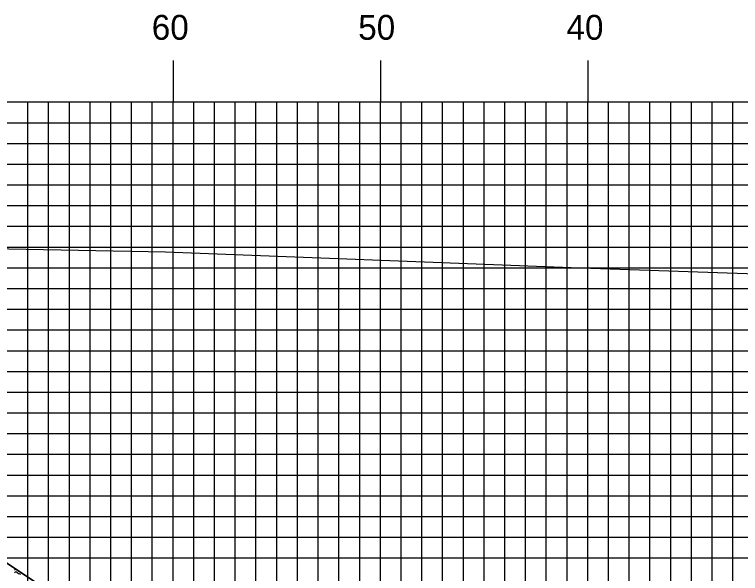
# Model space of a CAD drawing. Extents: x 1770055 to 1770398, y 442591 to 442811.
# Drawn here: x 1770152.88 to 1770187.89, y 442710.92 to 442737.88 of the extents above; entities that cross this region are included whole.
import ezdxf

# ---------------------------------------------------------------- set-up
doc = ezdxf.new("R2010")
doc.units = 0
for name, color, linetype in [('D_Roadway_Centerline', 7, 'Continuous'), ('D_Roadway_SlopeLines', 7, 'Continuous'), ('GRUBBING IN FILL', 7, 'Continuous'), ('H_V ANNOTATION', 7, 'Continuous'), ('MAJOR', 7, 'Continuous'), ('MINOR', 7, 'Continuous'), ('S_Roadway_Centerline', 7, 'Continuous')]:
    doc.layers.add(name, color=color, linetype=linetype)

msp = doc.modelspace()

# ---------------------------------------------------------------- linework, layer by layer
at = {"layer": 'D_Roadway_Centerline'}
msp.add_lwpolyline([(1770126.762, 442726.961), (1770128.012, 442726.836), (1770129.262, 442726.509), (1770130.512, 442725.979), (1770131.761, 442725.247), (1770143.721, 442717.274), (1770186.354, 442688.852), (1770190.354, 442689.852), (1770200.525, 442692.396), (1770200.528, 442692.396), (1770208.529, 442692.716), (1770210.349, 442692.753), (1770220.528, 442692.956), (1770232.528, 442692.716), (1770240.528, 442692.396), (1770250.702, 442689.852), (1770254.136, 442688.994)], dxfattribs=at)
at = {"layer": 'D_Roadway_SlopeLines'}
msp.add_lwpolyline([(1770186.354, 442688.852), (1770131.761, 442725.247), (1770130.512, 442725.979), (1770129.262, 442726.509), (1770128.012, 442726.836), (1770126.762, 442726.961)], dxfattribs=at)
at = {"layer": 'GRUBBING IN FILL'}
for p, q in [((1770152.947, 442711.123), (1770152.882, 442711.084)), ((1770152.882, 442710.95), (1770152.91, 442710.975)), ((1770152.995, 442710.979), (1770153.073, 442710.923)), ((1770153.085, 442710.917), (1770153.174, 442710.878))]:
    msp.add_line(p, q, dxfattribs=at)
for centre, major_axis, end_param in [((1770152.955, 442710.923), (0, 0.0683), 7.003256), ((1770153.113, 442710.979), (0, -0.0683), 5.870775)]:
    msp.add_ellipse(centre, major_axis=major_axis, ratio=0.99895, start_param=5.668522, end_param=end_param, dxfattribs=at)
at = {"layer": 'MAJOR'}
for p, q in [((1770160.528, 442735.669), (1770160.528, 442733.665)), ((1770170.528, 442735.669), (1770170.528, 442733.665)), ((1770180.528, 442735.669), (1770180.528, 442733.665)), ((1770080.528, 442733.665), (1770360.528, 442733.665)), ((1770080.528, 442733.665), (1770360.528, 442733.665)), ((1770160.528, 442683.665), (1770160.528, 442733.665)), ((1770170.528, 442683.665), (1770170.528, 442733.665)), ((1770180.528, 442683.665), (1770180.528, 442733.665)), ((1770080.528, 442728.665), (1770360.528, 442728.665)), ((1770080.528, 442723.665), (1770360.528, 442723.665)), ((1770080.528, 442718.665), (1770360.528, 442718.665)), ((1770080.528, 442713.665), (1770360.528, 442713.665))]:
    msp.add_line(p, q, dxfattribs=at)
at = {"layer": 'MINOR'}
for p, q in [((1770153.528, 442683.665), (1770153.528, 442733.665)), ((1770154.528, 442683.665), (1770154.528, 442733.665)), ((1770155.528, 442683.665), (1770155.528, 442733.665)), ((1770156.528, 442683.665), (1770156.528, 442733.665)), ((1770157.528, 442683.665), (1770157.528, 442733.665)), ((1770158.528, 442683.665), (1770158.528, 442733.665)), ((1770159.528, 442683.665), (1770159.528, 442733.665)), ((1770161.528, 442683.665), (1770161.528, 442733.665)), ((1770162.528, 442683.665), (1770162.528, 442733.665)), ((1770163.528, 442683.665), (1770163.528, 442733.665)), ((1770164.528, 442683.665), (1770164.528, 442733.665)), ((1770165.528, 442683.665), (1770165.528, 442733.665)), ((1770166.528, 442683.665), (1770166.528, 442733.665)), ((1770167.528, 442683.665), (1770167.528, 442733.665)), ((1770168.528, 442683.665), (1770168.528, 442733.665)), ((1770169.528, 442683.665), (1770169.528, 442733.665)), ((1770171.528, 442683.665), (1770171.528, 442733.665)), ((1770172.528, 442683.665), (1770172.528, 442733.665)), ((1770173.528, 442683.665), (1770173.528, 442733.665)), ((1770174.528, 442683.665), (1770174.528, 442733.665)), ((1770175.528, 442683.665), (1770175.528, 442733.665)), ((1770176.528, 442683.665), (1770176.528, 442733.665)), ((1770177.528, 442683.665), (1770177.528, 442733.665)), ((1770178.528, 442683.665), (1770178.528, 442733.665)), ((1770179.528, 442683.665), (1770179.528, 442733.665)), ((1770181.528, 442683.665), (1770181.528, 442733.665)), ((1770182.528, 442683.665), (1770182.528, 442733.665)), ((1770183.528, 442683.665), (1770183.528, 442733.665)), ((1770184.528, 442683.665), (1770184.528, 442733.665)), ((1770185.528, 442683.665), (1770185.528, 442733.665)), ((1770186.528, 442683.665), (1770186.528, 442733.665)), ((1770187.528, 442683.665), (1770187.528, 442733.665)), ((1770080.528, 442732.665), (1770360.528, 442732.665)), ((1770080.528, 442731.665), (1770360.528, 442731.665)), ((1770080.528, 442730.665), (1770360.528, 442730.665)), ((1770080.528, 442729.665), (1770360.528, 442729.665)), ((1770080.528, 442727.665), (1770360.528, 442727.665)), ((1770080.528, 442726.665), (1770360.528, 442726.665)), ((1770080.528, 442725.665), (1770360.528, 442725.665)), ((1770080.528, 442724.665), (1770360.528, 442724.665)), ((1770080.528, 442722.665), (1770360.528, 442722.665)), ((1770080.528, 442721.665), (1770360.528, 442721.665)), ((1770080.528, 442720.665), (1770360.528, 442720.665)), ((1770080.528, 442719.665), (1770360.528, 442719.665)), ((1770080.528, 442717.665), (1770360.528, 442717.665)), ((1770080.528, 442716.665), (1770360.528, 442716.665)), ((1770080.528, 442715.665), (1770360.528, 442715.665)), ((1770080.528, 442714.665), (1770360.528, 442714.665)), ((1770080.528, 442712.665), (1770360.528, 442712.665)), ((1770080.528, 442711.665), (1770360.528, 442711.665))]:
    msp.add_line(p, q, dxfattribs=at)
at = {"layer": 'S_Roadway_Centerline'}
msp.add_lwpolyline([(1770121.048, 442727.056), (1770126.39, 442726.968), (1770141.191, 442726.69), (1770144.283, 442726.671), (1770149.24, 442726.636), (1770160.165, 442726.44), (1770179.315, 442725.697), (1770179.585, 442725.683), (1770179.724, 442725.676), (1770199.014, 442725.017), (1770203.08, 442724.873), (1770209.671, 442724.387), (1770215.35, 442723.878), (1770218.936, 442723.678), (1770234.279, 442722.779), (1770238.306, 442722.542), (1770239.134, 442722.503), (1770240.342, 442722.476), (1770257.862, 442721.875)], dxfattribs=at)

# ---------------------------------------------------------------- texts
at = {"layer": 'H_V ANNOTATION'}
for s, p in [('60', (1770159.5, 442736.665)), ('50', (1770169.457, 442736.665)), ('40', (1770179.5, 442736.665))]:
    msp.add_text(s, height=1.2, dxfattribs=at).set_placement(p)

doc.saveas('drawing.dxf')
